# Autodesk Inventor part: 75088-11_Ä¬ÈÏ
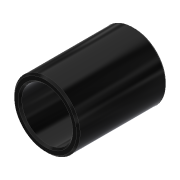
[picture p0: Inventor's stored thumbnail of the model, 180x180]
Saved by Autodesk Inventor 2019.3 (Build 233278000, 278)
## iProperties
Created: 2010-06
Part Number: 75088-11_Ä¬ÈÏ
Material: Ogólny
Document SubType Name: Modeling
Designer: CADENGINEERING4
Density: 1 g/cm^3
Appearance: Gładki — czarny
Author: CADENGINEERING4
Revision Number: ÈÎºÎ
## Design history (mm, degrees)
feature "NONE"
node "Bryła1"
